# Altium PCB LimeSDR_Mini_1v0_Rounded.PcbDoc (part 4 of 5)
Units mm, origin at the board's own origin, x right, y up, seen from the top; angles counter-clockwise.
Board outline 69.3 x 52.3 mm, 8 copper layers (Top, L2, L3, L4, L5, L6, L7, Bottom), stack 1.555 mm thick; 371 components, 281 nets, 1644 pads, 778 vias.
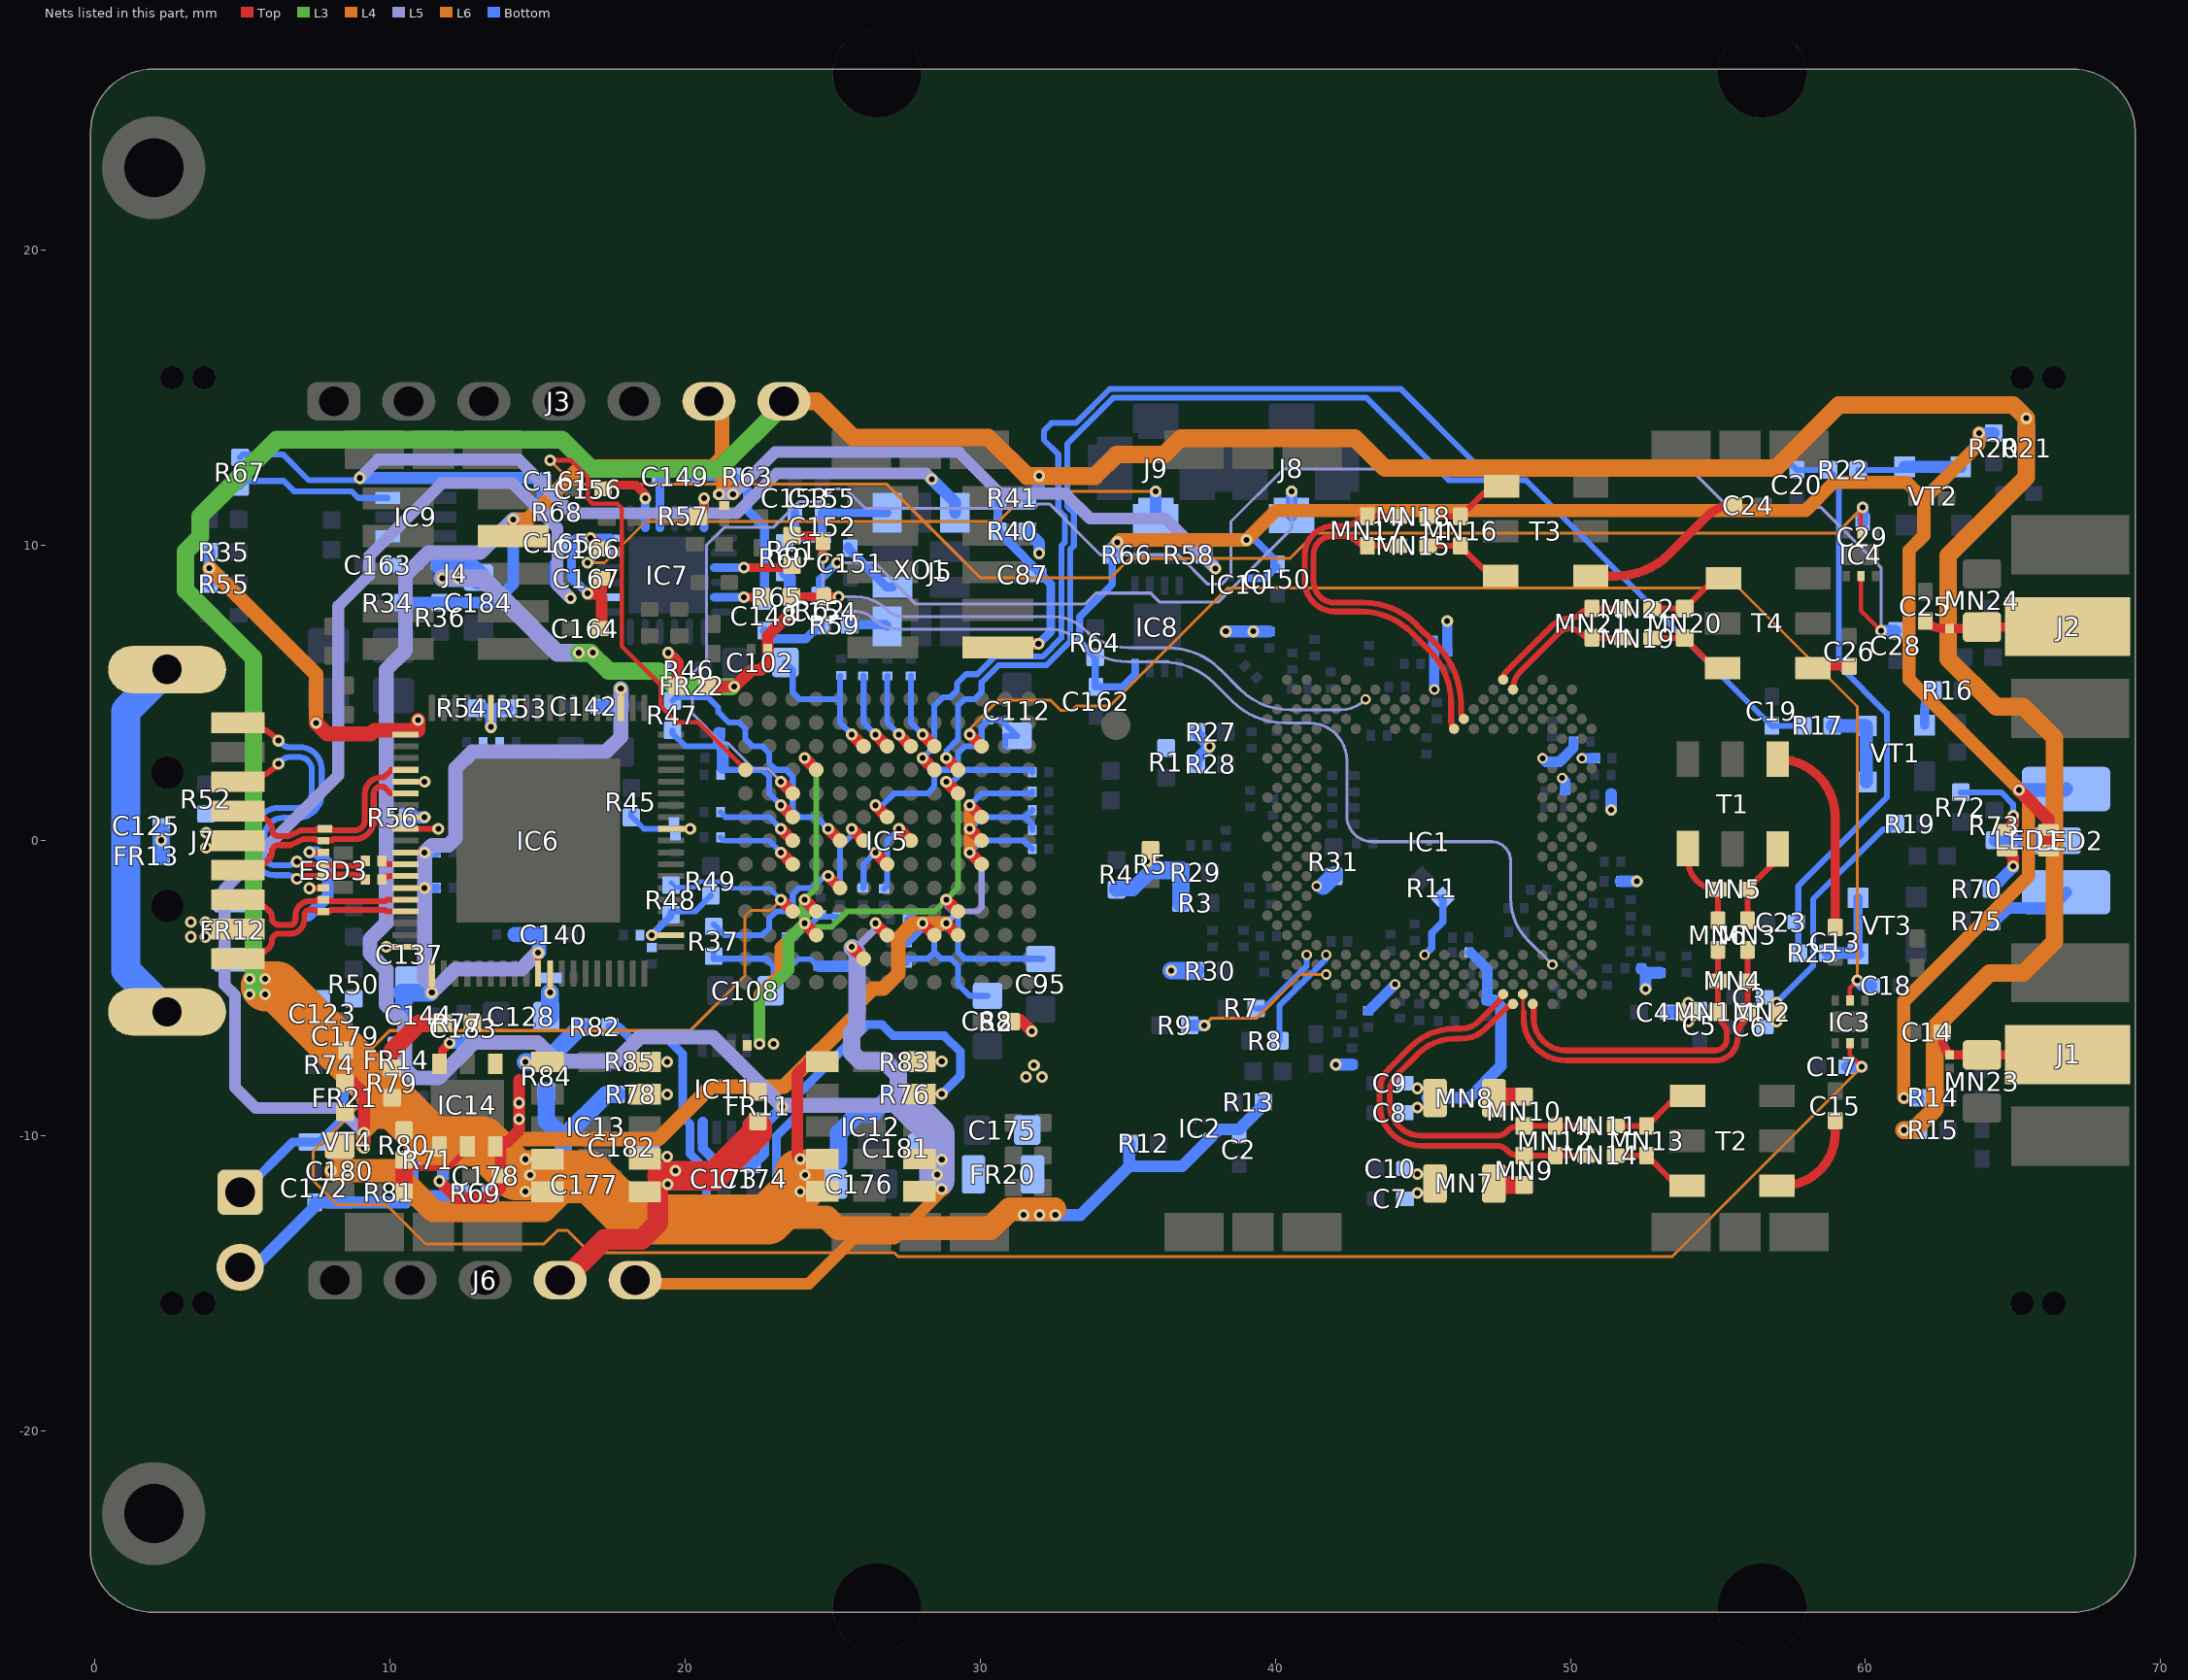
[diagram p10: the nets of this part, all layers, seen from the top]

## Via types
v1: diameter 0.4, hole 0.2, Top to Bottom, tented both sides, 544 vias
v2: diameter 0.4, hole 0.2, Top to Bottom, tented top, 113 vias
v3: diameter 0.35, hole 0.2, Top to Bottom, tented top, 87 vias
v4: diameter 0.5, hole 0.2, Top to Bottom, 25 vias
v5: diameter 0.5, hole 0.2, Top to Bottom, tented both sides, 8 vias
v6: diameter 0.35, hole 0.2, Top to Bottom, tented both sides, 1 vias

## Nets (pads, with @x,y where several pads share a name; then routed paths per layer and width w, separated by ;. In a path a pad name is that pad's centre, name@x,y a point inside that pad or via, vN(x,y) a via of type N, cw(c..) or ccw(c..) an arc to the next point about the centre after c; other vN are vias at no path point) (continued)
NetC82_1: C82.1 IC1.C21 | length 1.3
  Bottom w0.35: C82.1@43.15,-5.76 43.169,-5.76 v3(44.061,-4.868)
NetC83_1: C83.1 IC1.AF6 | length 1.5
  Bottom w0.35: v3(49.056,2.791) 49.173,2.674 49.635,2.674 50.108,3.147 C83.1@50.108,3.357
NetC84_1: C84.1 IC1.AF2 | length 0.5
  Bottom w0.35: v3(50.388,2.791) 50.844,2.791 C84.1@50.845,2.79
NetC85_1: C85.1 IC1.AD4 | length 0.5
  Bottom w0.35: v3(49.722,2.125) 49.825,2.022 C85.1@49.825,1.695
NetC86_1: C86.1 IC1.AN17 | length 1.6
  Bottom w0.34: C86.1@45.351,6.66 C86.1@45.351,6.768 ; C86.1@45.381,6.605 45.381,5.134 v3(45.393,5.122)
NetC87_2: C87.2 J5.10 R40.2 R41.2 | length 7.3
  Top w0.4: J5.10@30.6,6.515 30.75,6.665 v1(31.975,6.665)
  Bottom w0.3: R41.2@30.594,11.606 30.594,10.496 R40.2@30.6,10.49 32.4,8.69 32.4,7.09 v1(31.975,6.665)
NetC125_1: C125.1 FR13.2 J7.10 | length 12.8
  Bottom w1: J7.10@2.45,-5.8 1.05,-4.4 1.05,4.4 J7.10@2.45,5.8
NetC148_1: C148.1 C149.2 R63.2 | length 6.1
  Bottom w0.309: C149.2@20.175,12.34 R63.2@21.625,12.34 21.668,12.34 22.125,11.883 22.125,11.19 22.7,10.615 C148.1@22.7,8.115
NetC148_2: C148.2 R59.2 R62.2 | length 2.2
  Bottom w0.309: C148.2@22.7,7.115 22.975,6.84 24.09,6.84 24.568,7.318 R62.2@24.588,7.318
NetC149_1: C149.1 IC7.21 | length 1.8
  Bottom w0.3: IC7.21@19.15,10.6 IC7.21@19.15,10.925 19.15,12.315 C149.1@19.175,12.34
NetC151_2: C151.2 XO1.7 | length 2.1
  Bottom w0.3: C151.2@25.525,9.965 25.525,9.911 26.846,8.59 XO1.7@27.025,8.59
NetC153_2: C153.2 FR15.1 R60.1 | length 1.4
  Bottom w0.3: C153.2@23.725,11.115 23.725,10.265 FR15.1@24.245,10.265
NetC155_2: C155.2 FR15.2 XO1.9 | length 3.1
  Bottom w0.3: FR15.2@24.805,10.265 24.65,10.42 C155.2@24.65,11.115 XO1.9@26.85,11.115
NetC156_2: C156.2 IC7.20 | length 2.7
  Top w0.3: C156.2@17.225,11.915 17.36,12.05 18.336,12.05 18.65,11.736 v1(18.65,11.6)
  Bottom w0.3: IC7.20@18.65,10.6 IC7.20@18.65,10.925 v1(18.65,11.6)
NetC163_1: C163.1 FR17.2 IC9.4
NetC172_1: C172.1 J10.2 R69.2 R71.2 | length 9.8
  Bottom w0.4: J10.2@4.925,-14.455 5.403,-14.455 7.45,-12.408 C172.1@7.45,-12.26 10.545,-12.26 10.77,-12.035 ; R71.2@10.8,-10.835 10.77,-10.865 10.77,-12.035 ; R69.2@12.4,-11.935 12.3,-12.035 10.77,-12.035
NetC183_2: C183.2 IC14.3 | length 1.3
  Top w0.3: IC14.3@11.675,-7.56 11.775,-7.46 11.775,-7.11 v1(12.025,-6.86)
  Bottom w0.4: v1(12.025,-6.86) C183.2@12.5,-6.86
NetIC1_D28: IC1.D28 R9.1 | length 5.3
  L4 w0.1: v1(37.6,-6.257) 37.847,-6.01 39.375,-6.01 40.85,-4.535 v3(41.73,-4.535)
  Bottom w0.4: R9.1@37.1,-6.257 v1(37.6,-6.257)
NetIC1_F18: IC1.F18 R11.1 | length 2.2
  Bottom w0.25: v3(45.06,-3.869) 45.298,-3.631 45.298,-3.134 45.681,-2.751 45.681,-2.019 R11.1@45.63,-1.967
NetIC1_F28: IC1.F28 R8.1 | length 3.6
  Bottom w0.2: R8.1@40.15,-6.782 40.15,-5.585 41.73,-4.005 v3(41.73,-3.869)
NetIC1_F30: IC1.F30 R7.1 | length 2.7
  Bottom w0.2: R7.1@39.35,-5.682 39.628,-5.682 41.064,-4.246 v3(41.064,-3.869)
NetIC5_E5: IC5.E5 R37.2 | length 5.8
  Top w0.4: v2(24.85,-1.2) IC5.E5@25.25,-1.6
  Bottom w0.2: R37.2@20.975,-2.835 21.34,-3.2 22.616,-3.2 22.85,-2.966 22.85,-2.634 23.084,-2.4 23.416,-2.4 23.65,-2.166 23.65,-1.834 23.884,-1.6 24.322,-1.6 24.722,-1.2 v2(24.85,-1.2)
NetIC5_E7: IC5.E7 R47.2 | length 8.9
  Top w0.4: v2(24.85,0.4) IC5.E7@25.25,0
  Bottom w0.2: R47.2@19.575,4.74 19.7,4.865 20.766,4.865 21.125,4.506 21.125,4.359 21.484,4 21.84,4 22.05,3.79 22.05,3.434 22.284,3.2 22.616,3.2 22.85,2.966 22.85,2.634 23.084,2.4 23.416,2.4 23.65,2.166 23.65,1.034 23.884,0.8 24.45,0.8 v2(24.85,0.4)
NetIC6_27: IC6.27 R56.2 | length 1.2
  Top w0.2: IC6.27@10.525,0.8 v1(11.175,0.8)
  Bottom w0.4: R56.2@10.6,0.79 11.165,0.79 v1(11.175,0.8)
NetIC7_3: IC7.3 R61.2 | length 2.6
  Top w0.3: v1(22,9.25) 23.408,9.25 ccw(c23.408,9.557) R61.2@23.625,9.34
  Bottom w0.3: IC7.3@21,9.25 IC7.3@21.325,9.25 v1(22,9.25)
NetIC7_5: IC7.5 R65.2 | length 1.6
  Top w0.309: v1(22,8.25) 22.564,8.25 ccw(c22.564,8.301) R65.2@22.6,8.265
  Bottom w0.3: IC7.5@21,8.25 IC7.5@21.325,8.25 v1(22,8.25)
NetIC7_24: IC7.24 R57.1 | length 1.7
  Top w0.3: R57.1@20.45,10.99 20.65,11.19 v1(20.65,11.6)
  Bottom w0.3: IC7.24@20.65,10.6 IC7.24@20.65,10.925 v1(20.65,11.6)
NetIC9_6: IC9.6 R67.2 | length 5.3
  Bottom w0.2: R67.2@4.925,11.99 5.125,12.19 6.4,12.19 6.75,11.84 8.7,11.84 8.925,11.615 IC9.6@9.925,11.615
NetIC12_11: IC12.11 R83.2
  other v1: 28.701,-7.485
NetIC13_1: IC13.1 R82.1 R84.2 | length 2.4
  Bottom w0.6: v1(14.588,-7.495) 15.265,-7.495 R82.1@16.45,-6.31
NetIC13_10: IC13.10 R78.1
  other v1: 19.39,-8.595
NetIC13_11: IC13.11 R85.2
  other v1: 19.39,-7.495
NetIC14_4: IC14.4 R79.1 R80.2
NetIC14_5: IC14.5 R80.1 R81.1 | length 3.5
  Top w0.2: R80.1@10.6,-11.085 11.984,-11.085 12.625,-10.444 IC14.5@12.625,-10.36
  Top w0.6: R81.1@10.475,-11.91 R80.1@10.475,-10.81
NetJ7_7: J7.7 R52.2
  other v1: 3.775,-0.235 3.775,0.265
NetJ10_1: J10.1 R74.2 VT4.D | length 6.3
  Bottom w0.3: J10.1@4.925,-11.915 5.006,-11.915 6.711,-10.21 VT4.D@7.4,-10.21 7.625,-10.21 8.45,-9.385 R74.2@8.45,-7.61
NetLED1_3: LED1.3 R70.1 | length 1.7
  Top w0.4: LED1.3@64.8,-0.335 65,-0.535 v1(65,-0.86)
  Bottom w0.4: R70.1@64.275,-1.635 65,-0.91 v1(65,-0.86)
NetLED1_4: LED1.4 R72.1 | length 2.9
  Top w0.4: LED1.4@64.8,0.365 65,0.565 v1(65,0.84)
  Bottom w0.2: R72.1@63.225,1.64 64.598,1.64 65,1.238 v1(65,0.84)
NetLED2_C1: LED2.C1 R75.1 | length 3.1
  Bottom w0.4: R75.1@64.15,-2.735 64.375,-2.735 64.825,-2.285 66.265,-2.285 LED2.C1@66.8,-1.75
NetLED2_C2: LED2.C2 R73.1 | length 1.9
  Bottom w0.4: R73.1@64.375,0.015 64.39,0 LED2.C2@66.3,0
NetMN7_1: MN7.1 MN9.2 | length 1
  Top w0.6: MN7.1@47.412,-11.618 47.464,-11.67 MN9.2@48.435,-11.67
NetMN8_1: MN8.1 MN10.2 | length 1
  Top w0.6: MN8.1@47.412,-8.718 47.46,-8.67 MN10.2@48.435,-8.67
NetR16_2: R16.2 VT1.2 | length 1.3
  Bottom w0.309: VT1.2@62,3.915 62,4.408 cw(c62.982,4.408) R16.2@62.287,5.102
NetR17_1: R17.1 VT1.3 VT1.4 | length 3
  Bottom w0.45: R17.1@58.875,3.89 VT1.3@60.025,3.89 VT1.4@60.025,1.99
NetR22_2: R22.2 VT2.3 VT2.4 | length 3.5
  Bottom w0.2: R22.2@59.75,12.565 61.225,12.565 VT2.4@61.325,12.665
  Bottom w0.4: VT2.4@61.325,12.665 VT2.3@63.225,12.665
NetR25_1: R25.1 VT3.3 VT3.4 | length 2.9
  Bottom w0.309: VT3.4@59.75,-3.835 VT3.3@59.75,-1.935
  Bottom w0.4: R25.1@58.725,-3.81 59.725,-3.81 VT3.4@59.75,-3.835
NetR59_1: R59.1 XO1.6 | length 1.3
  Bottom w0.309: R59.1@25.575,7.315 26.8,7.315 XO1.6@26.85,7.265
PG_VCC1P8: IC12.10 R76.1 R82.2 | length 23.3
  Bottom w0.3: R82.2@17.45,-6.31 17.75,-6.31 18.125,-6.685 19.375,-6.685 19.925,-7.235 19.925,-9.36 20.175,-9.61 20.175,-9.91 20.175,-10.611 20.725,-11.161 20.725,-12.234 21.076,-12.585 22.574,-12.585 23.1,-12.059 23.1,-10.01 23.825,-9.285 23.825,-8.585 26.175,-6.235 26.676,-6.235 27.051,-6.61 28.787,-6.61 29.336,-7.159 29.336,-7.95 v1(28.701,-8.585)
REF_CLK_IN: J8.1 R62.1 | length 20.7
  L5 w0.1: v1(25.15,9.415) 26.425,9.415 27.825,8.015 33.55,8.015 33.925,8.39 35.775,8.39 36.075,8.09 38.075,8.09 40.55,10.565 v1(40.55,11.84)
  Bottom w0.3: R62.1@24.588,8.317 24.588,8.853 v1(25.15,9.415)
  Bottom w0.4: J8.1@40.55,11.015 v1(40.55,11.84)
REF_CLK_OUT: IC7.17 J9.1 | length 22
  L6 w0.1: v1(16.7,9.415) 17.275,9.415 18.675,10.815 30.625,10.815 31.65,11.84 v1(35.95,11.84)
  Bottom w0.25: v1(16.7,9.415) 17.035,9.75 IC7.17@17.475,9.75
  Bottom w0.4: J9.1@35.95,11.015 v1(35.95,11.84)
RFSW_RX_V1: C29.2 IC4.5 IC5.A10 | length 63
  Top w0.15: v1(15.425,12.89) 16.125,12.89 16.7,12.315 16.7,11.59 16.875,11.415 17.7,11.415 17.85,11.265 17.85,6.6 19.175,5.275 19.175,4.565 19.725,4.015 20.435,4.015 IC5.A10@22.05,2.4 ; IC4.5@59.85,10.415 v1@59.85,11.29
  L4 w0.1: v1(15.425,12.89) 16.225,12.09 26.825,12.09 30,8.915 34.425,8.915 35.075,9.565 40.5,9.565 41.35,10.415 59.025,10.415 v1(59.9,11.29)
  Bottom w0.4: C29.2@59.9,10.79 v1(59.9,11.29)
RFSW_RX_V2: C28.2 IC4.2 IC5.C9 | length 61.3
  Top w0.15: IC4.2@59.85,8.965 59.85,7.79 v1(60.525,7.115)
  Top w0.4: v2(23.25,2) IC5.C9@23.65,1.6
  L5 w0.1: v2(23.25,2) 22.81,2.44 22.315,2.44 21.44,3.315 21.24,3.315 20.25,4.305 20.25,5.67 20.725,6.145 20.725,10.015 21.325,10.615 22.992,10.615 23.867,11.49 24.59,11.49 25.025,11.925 25.44,11.925 26.1,11.265 31.825,11.265 31.975,11.415 32.35,11.415 34.075,9.69 36.72,9.69 37.72,8.69 38.175,8.69 38.5,9.015 38.5,10.815 40.275,12.59 54.075,12.59 55.375,11.29 58.5,11.29 60.525,9.265 v1(60.525,7.115)
  Bottom w0.4: v1(60.525,7.115) C28.2@61.025,7.115
RFSW_TX_V1: C18.2 IC3.5 IC5.L11 | length 45.4
  Top w0.15: IC3.5@59.475,-5.41 59.475,-4.985 v1(59.725,-4.735)
  Top w0.4: v2(29.65,3.6) IC5.L11@30.05,3.2
  L4 w0.1: v2(29.65,3.6) 29.65,3.79 30.625,4.765 32.38,4.765 32.73,4.415 33.1,4.415 33.25,4.565 34.391,4.565 38.391,8.565 55.709,8.565 59.725,4.549 v1(59.725,-4.735)
  Bottom w0.4: v1(59.725,-4.735) 59.9,-4.91 C18.2@60.2,-4.91
RFSW_TX_V2: C17.2 IC3.2 IC5.C4 R48.2 | length 85.2
  Top w0.15: IC3.2@59.475,-6.86 59.475,-7.26 v1(59.875,-7.66)
  Top w0.4: v2(23.25,-2) IC5.C4@23.65,-2.4
  L6 w0.1: v2(23.25,-2) 22.89,-2.36 22.225,-2.36 22.025,-2.56 22.025,-4.585 20.175,-6.435 9.991,-6.435 8.925,-7.501 8.925,-9.01 7.4,-10.535 7.4,-11.519 8.216,-12.335 9.875,-12.335 11.2,-13.66 15.225,-13.66 15.675,-13.21 16.025,-13.21 16.775,-13.96 27.085,-13.96 27.225,-14.1 53.435,-14.1 v1(59.875,-7.66)
  Bottom w0.15: R48.2@19.525,-1.41 19.69,-1.575 20.33,-1.575 20.52,-1.385 21.212,-1.385 21.437,-1.61 22.86,-1.61 v2(23.25,-2)
  Bottom w0.4: C17.2@59.375,-7.66 v1(59.875,-7.66)
RX: C25.2 ESD2.1 J2.1 MN24.1 | length 4.9
  Top w0.309: C25.2@62.025,7.44 62.028,7.437 ccw(c62.625,8.035) 62.625,7.19 ESD2.1@62.85,7.19 63.829,7.19 ccw(c63.829,7.361) MN24.1@63.95,7.24 66.815,7.24 ccw(c66.815,7.283) J2.1@66.845,7.252
RX1_H: C24.2 T3.4 | length 5.7
  Top w0.309: T3.4@50.69,8.97 51.553,8.97 ccw(c51.553,11.51) 53.349,9.714 54.629,10.994 cw(c55.525,10.098) C24.2@55.525,11.365
RX1_H_A_N: IC1.AJ15 MN17.1 MN18.2 | length 12.9
  Top w0.2: MN17.1@43.132,10.99 MN17.1@43.125,10.99 ; MN18.2@44.175,10.99 MN17.1@43.125,10.99 ; IC1.AJ15@46.059,3.79 cw(c46.3,4.031) 45.959,4.031 45.959,4.656 ccw(c43.394,4.656) 45.208,6.47 44.636,7.042 ccw(c42.89,5.295) 42.89,7.765 42.025,7.765 cw(c42.025,8.79) 41,8.79 41,9.69 cw(c41.97,9.69) 41.97,10.66 42.328,10.66 ccw(c42.328,11.279) 42.766,10.841 cw(c43.125,10.482) MN17.1@43.125,10.99
RX1_H_A_P: IC1.AK14 MN15.2 MN17.2 | length 12
  Top w0.2: MN15.2@44.175,9.99 MN17.2@43.125,9.99 cw(c43.125,10.498) 42.766,10.139 ccw(c42.328,9.701) 42.328,10.32 41.93,10.32 ccw(c41.93,9.69) 41.3,9.69 41.3,8.79 ccw(c42.025,8.79) 42.025,8.065 42.999,8.065 cw(c42.999,5.544) 44.782,7.327 45.448,6.66 cw(c43.411,4.623) 46.292,4.623 46.292,4.54 46.292,4.364 ccw(c46.633,4.364) IC1.AK14@46.392,4.123
RX1_H_B_N: MN16.1 MN18.1 T3.2 | length 2.8
  Top w0.2: MN18.1@45.175,10.99 MN16.1@46.225,10.99 ; MN16.1@46.275,10.99 47.033,11.748 cw(c47.665,11.117) T3.2@47.665,12.01
RX1_H_B_P: MN15.1 MN16.2 T3.1 | length 2.8
  Top w0.2: MN15.1@45.175,9.99 45.575,9.99 MN16.2@46.225,9.99 ; MN16.2@46.275,9.99 47.051,9.214 ccw(c47.64,9.803) T3.1@47.64,8.97
RX1_W: C26.2 T4.4 | length 1.3
  Top w0.309: T4.4@58.225,5.821 ccw(c58.191,5.821) T4.4@58.215,5.845 cw(c58.384,5.676) 58.384,5.915 C26.2@59.45,5.915
RX2_W_A_N: IC1.AP10 MN21.1 MN22.2 | length 5
  Top w0.2: IC1.AP10@47.739,5.47 IC1.AP10@47.724,5.455 cw(c48.147,5.455) 47.848,5.754 48.85,6.757 49.384,7.291 cw(c49.974,6.701) 49.974,7.535 ccw(c49.974,8.043) 50.333,7.684 ; 50.366,7.716 cw(c50.725,7.357) MN21.1@50.725,7.865 ; MN21.1@50.732,7.865 MN22.2@51.775,7.865
RX2_W_A_P: IC1.AN9 MN19.2 MN21.2 | length 4.8
  Top w0.2: IC1.AN9@48.072,5.137 IC1.AN9@48.057,5.122 cw(c48.928,5.122) 48.312,5.738 49.625,7.05 cw(c49.974,6.701) 49.974,7.195 cw(c49.974,6.687) 50.333,7.046 50.366,7.014 ccw(c50.725,7.373) 50.725,6.865 MN19.2@51.775,6.865
RX2_W_B_N: MN20.1 MN22.1 T4.2 | length 2.8
  Top w0.2: MN22.1@52.775,7.865 MN20.1@53.825,7.865 ; MN20.1@53.875,7.865 54.633,8.623 cw(c55.265,7.992) T4.2@55.265,8.885
RX2_W_B_P: MN19.1 MN20.2 T4.1 | length 3.2
  Top w0.2: MN19.1@52.775,6.865 53.175,6.865 MN20.2@53.825,6.865 ; MN20.2@53.875,6.865 54.633,6.107 ccw(c55.265,6.738) T4.1@55.265,5.845 ; T4.1@54.87,5.845 T4.1@55.215,5.845
RXPLL_CLK: C154.2 IC1.AM24 R65.1 | length 20.7
  Top w0.309: R65.1@23.6,8.265 C154.2@24.717,8.265 ; C154.2@24.7,8.265 v1(25.2,8.265)
  L5 w0.1: v1(25.2,8.265) 25.799,8.265 cw(c25.799,6.814) 26.825,7.84 ccw(c27.429,8.444) 27.429,7.59 32.499,7.59 cw(c32.499,6.139) 33.525,7.165 ccw(c35.034,8.674) 35.034,6.54 36.348,6.54 cw(c36.348,4) 38.144,5.796 38.806,5.134 ccw(c40.504,6.832) 40.504,4.431 42.203,4.431 ccw(c42.203,5.639) v3@43.057,4.784
  other v3: 43.062,4.789
TCXO_VC: C161.2 R67.1 R68.1 XO1.1 | length 34.3
  L5 w0.4: v1(8.975,12.29) 9.6,12.915 14.363,12.915 16.178,11.1 21.76,11.1 23.1,12.44 28.175,12.44 v1(28.365,12.25)
  Bottom w0.2: R67.1@4.925,12.99 5.025,13.09 6.375,13.09 7.25,12.215 8.9,12.215 v1(8.975,12.29)
  Bottom w0.4: v1(8.975,12.29) 15.075,12.29 C161.2@15.175,12.19 R68.1@15.175,11.14 ; v1(28.365,12.25) 29.15,11.465 XO1.1@29.15,11.115
TX: C14.2 ESD1.1 J1.1 MN23.1 | length 4.8
  Top w0.309: C14.2@62.6,-6.485 62.6,-6.656 ccw(c63.454,-6.656) ESD1.1@62.85,-7.26 MN23.1@63.95,-7.26 66.815,-7.26 ccw(c66.815,-7.217) J1.1@66.845,-7.248
TX1_1: C13.2 T1.4 | length 6.8
  Top w0.309: T1.4@57.02,2.765 cw(c57.02,0.81) 58.975,0.81 C13.2@58.975,-2.935
TX1_1_A_N: IC1.A7 MN1.1 MN4.1 MN6.2 | length 11.1
  Top w0.2: IC1.A7@48.723,-5.584 48.757,-5.618 48.757,-6.01 ccw(c49.857,-6.01) 49.857,-7.11 54.9,-7.11 ccw(c54.9,-6.706) 55.304,-6.706 55.304,-6.539 ccw(c54.796,-6.539) 55.155,-6.18 ; IC1.A7@48.723,-5.534 IC1.A7@48.758,-5.569 ; MN1.1@55,-5.99 55,-5.808 MN4.1@55,-4.75 MN6.2@55,-3.7 ; MN1.1@55.001,-5.815 ccw(c55.509,-5.815) 55.149,-6.175
TX1_1_A_P: IC1.B8 MN2.1 MN3.1 MN4.2 | length 12.3
  Top w0.11: 48.39,-5.769 48.39,-5.557 IC1.B8@48.39,-5.201
  Top w0.2: 48.414,-5.804 48.414,-6.01 ccw(c49.854,-6.01) 49.854,-7.45 54.9,-7.45 ccw(c54.9,-6.679) 55.671,-6.679 55.671,-6.566 cw(c56.179,-6.566) 55.819,-6.207 55.852,-6.175 ccw(c55.493,-5.815) MN2.1@56.001,-5.815 ; MN2.1@56,-5.8 56,-5.4 MN4.2@56,-4.75 MN3.1@56,-3.7
TX1_1_B_N: MN5.2 MN6.1 T1.2 | length 2.7
  Top w0.2: T1.2@53.98,-0.63 ccw(c55,-0.63) MN5.2@55,-1.65 MN6.1@55,-2.7
TX1_1_B_P: MN3.2 MN5.1 T1.1 | length 2.8
  Top w0.2: MN3.2@56,-2.7 MN5.1@56,-1.65 56.776,-0.874 ccw(c56.187,-0.285) T1.1@57.02,-0.285
TX1_2: C15.2 T2.4 | length 3.5
  Top w0.309: T2.4@57.049,-11.71 cw(c57.049,-11.642) T2.4@57,-11.69 57.195,-11.69 ccw(c57.195,-9.91) 58.975,-9.91 C15.2@58.975,-9.485
TX2_1_A_N: IC1.B10 MN9.1 MN12.2 MN14.1 | length 14
  Top w0.2: IC1.B10@47.724,-5.201 47.689,-5.236 ccw(c47.848,-5.394) 47.624,-5.394 46.891,-6.126 cw(c46.303,-5.538) 46.303,-6.37 46.075,-6.37 ccw(c46.075,-8.46) 44.597,-6.982 43.885,-7.695 ccw(c44.729,-8.539) 43.535,-8.539 43.535,-8.925 ccw(c44.95,-8.925) 44.95,-10.34 47.495,-10.34 cw(c47.495,-10.848) 47.854,-10.489 47.886,-10.521 ccw(c48.246,-10.162) 48.246,-10.67 MN9.1@48.435,-10.67 MN12.2@49.485,-10.67 MN14.1@50.535,-10.67
TX2_1_A_P: IC1.A9 MN10.1 MN11.2 MN12.1 | length 13.2
  Top w0.2: IC1.A9@48.057,-5.534 48.022,-5.569 cw(c47.864,-5.411) 47.864,-5.634 47.128,-6.37 cw(c46.308,-5.549) 46.308,-6.71 46.075,-6.71 ccw(c46.075,-8.46) 44.837,-7.223 44.125,-7.935 ccw(c44.729,-8.539) 43.875,-8.539 43.875,-8.925 ccw(c44.95,-8.925) 44.95,-10 47.495,-10 ccw(c47.495,-9.492) 47.854,-9.851 47.886,-9.819 cw(c48.246,-10.178) 48.246,-9.67 MN10.1@48.435,-9.67 48.835,-9.67 MN12.1@49.485,-9.67 MN11.2@50.535,-9.67
TX2_1_B_N: MN13.1 MN14.2 T2.1 | length 3.2
  Top w0.2: MN14.2@51.535,-10.67 51.935,-10.67 MN13.1@52.585,-10.67 53.344,-11.428 ccw(c53.975,-10.797) T2.1@53.975,-11.69 ; T2.1@53.605,-11.69 T2.1@53.95,-11.69
TX2_1_B_P: MN11.1 MN13.2 T2.2 | length 2.8
  Top w0.2: MN11.1@51.535,-9.67 MN13.2@52.585,-9.67 53.344,-8.912 cw(c53.975,-9.543) T2.2@53.975,-8.65
TX_LB_AT: C19.1 IC5.K10 R17.2 | length 44.4
  Top w0.4: v2(28.85,2.8) IC5.K10@29.25,2.4
  Bottom w0.2: v2(28.85,2.8) 28.85,3.034 29.25,3.434 29.25,3.766 29.25,4.566 29.484,4.8 29.816,4.8 30.05,5.034 30.05,5.366 30.624,5.94 32.24,5.94 33.05,6.75 33.05,9.866 33.175,9.991 33.175,11.099 32.95,11.324 32.95,13.44 34.525,15.015 43.075,15.015 45.875,12.215 48.5,12.215 C19.1@56.825,3.89 R17.2@57.875,3.89
TX_LB_SH: C20.1 C23.1 IC5.J10 R22.1 R25.2 | length 62
  Top w0.4: v2(28.05,2.8) IC5.J10@28.45,2.4
  Bottom w0.2: v2(28.05,2.8) 28.45,3.2 28.45,4.566 28.749,4.865 28.991,4.865 29.225,5.099 29.225,5.341 29.525,5.641 29.901,5.641 30.5,6.24 32.116,6.24 32.75,6.874 32.75,9.99 32.875,10.115 32.875,10.975 32.65,11.2 32.65,13.09 32.159,13.581 32.159,13.89 32.419,14.15 33.236,14.15 34.401,15.315 44.25,15.315 46.775,12.79 57.45,12.79 C20.1@57.675,12.565 R22.1@58.75,12.565 59.1,12.215 59.1,5.94 60.725,4.315 60.725,1.465 57.725,-1.535 R25.2@57.725,-3.81
TXPLL_CLK: C152.2 IC1.E5 R61.1 | length 35.1
  Top w0.309: R61.1@23.625,10.34 24.192,10.34 cw(c24.192,9.657) C152.2@24.675,10.14 v1(24.675,9.59)
  L5 w0.1: v1(24.675,9.59) 24.675,8.29 ccw(c25.2,8.29) 25.2,7.765 25.789,7.765 cw(c25.789,6.93) 26.379,7.521 ccw(c27.238,8.379) 26.501,7.414 ccw(c27.238,8.379) 27.238,7.165 32.451,7.165 cw(c32.451,6.141) 33.175,6.865 33.231,6.809 ccw(c35.027,8.605) 35.027,6.065 36.148,6.065 cw(c36.148,3.525) 37.944,5.321 38.531,4.734 ccw(c40.327,6.53) 40.327,3.99 41.15,3.99 cw(c41.15,2.715) 42.425,2.715 42.425,0.84 ccw(c43.3,0.84) 43.3,-0.035 47.325,-0.035 cw(c47.325,-0.685) 47.975,-0.685 47.975,-1.96 ccw(c49.974,-1.96) 48.56,-3.373 v3(49.389,-4.202)
USB_D_N: ESD3.2 IC6.25 J7.2 | length 7.6
  Top w0.2: J7.2@4.85,-1 5.022,-1 ccw(c5.022,0.238) 5.897,-0.638 ccw(c5.65,-0.39) 6,-0.39 cw(c6.24,-0.39) 6.24,-0.15 6.625,-0.15 7.05,0.05 7.48,0.05 7.53,0 ESD3.2@7.742,0 ; ESD3.2@7.818,0 8.03,0 8.08,0.05 8.805,0.05 ccw(c8.805,0.695) 9.45,0.695 9.45,1.59 cw(c9.695,1.59) 9.695,1.835 ; 9.7,1.835 cw(c9.7,1.618) 9.853,1.772 10.025,1.6 IC6.25@10.525,1.6
USB_D_P: ESD3.1 IC6.23 J7.3 | length 8.2
  Top w0.2: J7.3@4.65,0.965 4.685,1 J7.3@4.85,1 J7.3@5.022,1 ; J7.3@5.39,1 J7.3@5.022,1 ; ESD3.1@7.742,0.4 7.53,0.4 7.48,0.35 6.975,0.35 6.55,0.15 6.24,0.15 cw(c6.24,0.39) 6,0.39 ccw(c5.65,0.39) 5.897,0.638 ccw(c5.022,-0.238) J7.3@5.022,1 ; ESD3.1@7.818,0.4 8.03,0.4 8.08,0.35 8.805,0.35 ccw(c8.805,0.695) 9.15,0.695 9.15,1.59 cw(c9.7,1.59) 9.7,2.14 ccw(c9.7,2.357) 9.853,2.203 10.05,2.4 IC6.23@10.525,2.4
USB_GND: C125.2 ESD3.6 FR13.1 NT1.1 | length 1.3
  Top w0.2: v1(7.275,-1.615) cw(c7.311,-1.651) 7.311,-1.6 ESD3.6@7.742,-1.6
  Bottom w0.6: FR13.1@2.252,-0.515 C125.2@2.252,0.29
  other v1: 2.25,0.015
USB_SSRX_N: ESD3.7 IC6.34 J7.8 | length 7.2
  Top w0.2: J7.8@5.39,-2 J7.8@4.85,-2 5.022,-2 cw(c5.022,-3.238) 5.897,-2.362 cw(c5.65,-2.61) 6,-2.61 ccw(c6.24,-2.61) 6.24,-2.85 6.625,-2.85 ccw(c6.625,-2.675) 6.8,-2.675 6.8,-2.535 cw(c7.285,-2.535) 7.285,-2.05 7.48,-2.05 7.53,-2 ESD3.7@7.742,-2 7.955,-2 8.005,-2.05 9.85,-2.05 9.9,-2 IC6.34@10.525,-2
USB_SSRX_P: ESD3.8 IC6.35 J7.9 | length 6.7
  Top w0.2: J7.9@4.2,-4 J7.9@4.372,-4 ; J7.9@5.022,-4 ccw(c5.022,-2.762) 5.897,-3.638 ccw(c5.65,-3.39) 6,-3.39 cw(c6.24,-3.39) 6.24,-3.15 6.625,-3.15 ccw(c6.625,-2.675) 7.1,-2.675 7.1,-2.535 cw(c7.285,-2.535) 7.285,-2.35 7.48,-2.35 7.53,-2.4 ESD3.8@7.742,-2.4 7.955,-2.4 8.005,-2.35 9.85,-2.35 9.9,-2.4 IC6.35@10.525,-2.4
USB_SSTX_N: C121.1 ESD3.4 J7.5 | length 11.5
  Top w0.2: J7.5@4.85,4 cw(c4.85,2.153) 6.156,3.459 v1(6.225,3.39) ; v1(6.85,-0.71) ccw(c7.067,-0.493) 7.067,-0.8 ESD3.4@7.742,-0.8 7.955,-0.8 8.005,-0.85 8.772,-0.85 ccw(c8.772,-0.287) C121.1@9.17,-0.685 C121.1@9.153,-0.685
  Bottom w0.2: v1(6.225,3.39) 6.335,3.28 ccw(c6.6,3.544) 6.6,3.17 6.935,3.17 cw(c6.935,2.415) 7.69,2.415 7.69,1.59 cw(c6.875,1.59) 6.875,0.775 6.385,0.775 ccw(c6.385,0.14) 5.75,0.14 5.75,-0.48 ccw(c6.1,-0.48) 6.1,-0.83 6.56,-0.83 ccw(c6.56,-0.42) v1(6.85,-0.71)
USB_SSTX_P: C122.1 ESD3.5 J7.6 | length 11.5
  Top w0.2: J7.6@4.85,2 ccw(c4.85,3.847) 6.156,2.541 v1(6.225,2.61) ; v1(6.85,-1.29) cw(c7.067,-1.507) 7.067,-1.2 ESD3.5@7.742,-1.2 7.955,-1.2 8.005,-1.15 8.772,-1.15 cw(c8.772,-1.713) C122.1@9.17,-1.315 C122.1@9.153,-1.315
  Bottom w0.2: v1(6.225,2.61) 6.335,2.72 cw(c6.6,2.456) 6.6,2.83 6.935,2.83 cw(c6.935,2.415) 7.35,2.415 7.35,1.59 cw(c6.875,1.59) 6.875,1.115 6.244,1.115 ccw(c6.244,0.281) 5.41,0.281 5.41,-0.48 ccw(c6.1,-0.48) 6.1,-1.17 6.56,-1.17 cw(c6.56,-1.58) v1(6.85,-1.29)
USB_SSTXI_N: C121.2 IC6.31 | length 0.8
  Top w0.2: C121.2@9.73,-0.685 ccw(c10.008,-0.407) 10.008,-0.8 IC6.31@10.525,-0.8
USB_SSTXI_P: C122.2 IC6.32 | length 0.8
  Top w0.2: C122.2@9.73,-1.315 cw(c10.008,-1.593) 10.008,-1.2 IC6.32@10.525,-1.2
USB_VBUS: C123.1 ESD3.3 FR12.1 J7.1 R50.2 | length 3.3
  Top w0.2: v1(7.275,-0.385) ccw(c7.311,-0.349) 7.311,-0.4 ESD3.3@7.742,-0.4
  Bottom w0.4: 7.238,-2.548 7.9,-1.885 7.9,-0.76 7.525,-0.385 v1(7.275,-0.385)
  other v1: 3.25,-3.26 3.75,-3.26 3.25,-2.76 3.75,-2.76
VCC1P8: C108.2 C109.1 C110.1 C111.1 C173.2 C174.1 C181.2 FR16.1 FR20.1 IC5.F2 IC5.G3 IC11.8 IC12.7 IC12.8 J3.6 J4.4 J6.5 R34.2 R36.2 R37.1 R58.2 | length 114.3
  Top w0.4: J4.4@14.175,10.325 v1(14.175,10.88) ; v1(25.65,-3.6) IC5.F2@26.05,-4 ; v1(26.45,-2.8) IC5.G3@26.85,-3.2
  L4 w0.4: J6.5@18.311,-15.01 24.2,-15.01 25.725,-13.485 27.101,-13.485 v1@28.701,-11.885
  L5 w0.25: v1@25.84,-3.6 26.45,-2.99 v1(26.45,-2.8)
  L5 w0.4: v1(21.15,11.74) v1(21.625,11.74) 23.05,13.165 29.275,13.165 30.675,11.765 32.875,11.765 33.725,10.915 36.275,10.915 v1(37.975,9.215) ; v1@25.775,-3.725 v1(25.65,-3.6) v1@25.84,-3.6
  L5 w0.5: v1(14.175,10.88) 13.06,9.765 11.3,9.765 10.525,8.99 10.525,6.44 9.875,5.79 9.875,-2.785 9.325,-3.335 9.325,-3.828 9.875,-4.378 9.875,-5.563 10.5,-6.188 10.5,-7.705 10.83,-8.035 11.647,-8.035 12.847,-6.835 15,-6.835 15.634,-7.469 17.672,-7.469 18.481,-6.66 20.95,-6.66 23.26,-8.97 26.89,-8.97 27.225,-8.635
  L5 w0.6: v1@25.675,-3.635 25.825,-3.785 25.825,-6.335 25.65,-6.51 25.65,-7.185 25.925,-7.46 26.75,-7.46 27.225,-7.935 27.225,-8.635
  L5 w1.2: 27.425,-8.81 28.539,-9.924 v1@28.539,-11.51
  L6 w0.5: v1(14.175,10.88) 14.665,10.88 16.46,12.675 20.94,12.675 ; J3.6@20.811,14.89 21.25,14.451 21.25,12.985 20.94,12.675 ; 21.4,11.815 21.3,11.915 21.3,12.315 21,12.615 20.94,12.675
  Bottom w0.17: 22.995,-4.255 23.1,-4.15 23.702,-4.15 23.837,-4.015 24.285,-4.015 C110.1@24.525,-4.255
  Bottom w0.2: R37.1@20.975,-3.835 20.975,-4 22.74,-4 22.995,-4.255 C108.2@22.995,-5.235
  Bottom w0.35: IC11.8@20.6,-9.535 20.6,-10.435 21.125,-10.96 C174.1@22.325,-10.96 22.675,-10.61 22.675,-9.635 v1(23.3,-9.01)
  Bottom w0.4: R34.2@10.425,8.065 13.55,8.065 14.175,8.69 v1(14.175,10.88) ; C110.1@24.544,-4.255 C109.1@25.2,-4.255 25.775,-4.255 25.775,-3.725 v1(25.65,-3.6) ; R58.2@37.575,9.69 v1@37.9,9.365
  other v1: 28.701,-11.81 28.539,-11.32 28.701,-10.81
VCC1P8_LMS: C3.1 C4.2 C5.1 C6.2 C7.1 C8.1 C9.2 C10.2 C175.2 FR1.2 FR2.1 FR3.1 FR4.2 FR5.2 FR6.2 FR7.2 FR8.2 FR20.2 MN1.2 MN2.2 MN7.2 MN8.2 R19.2 R26.2 R32.2 R33.1 | length 21.2
  Bottom w0.2: v1(56.985,-5.485) 58.225,-4.245 58.225,-1.985 60.588,0.378 60.812,0.378 R19.2@61.012,0.577
  Bottom w0.35: FR4.2@45.826,6.391 v1(45.826,7.441) ; FR6.2@46.614,-3.785 47.185,-4.356 FR7.2@47.185,-4.51 FR8.2@47.185,-5.405
  Bottom w0.4: v1(38.325,7.091) R33.1@39.801,7.091 ; v1(42.056,-7.589) R26.2@42.606,-7.589 ; 45.142,-8.718 46.567,-8.718 47.65,-7.635 47.65,-5.635 47.42,-5.405 FR8.2@47.175,-5.405 ; v1(51.38,1.04) FR3.1@51.38,1.59 ; FR2.1@51.704,-1.376 v1(52.254,-1.376) ; FR1.2@52.411,-4.334 FR1.2@52.555,-4.478 ; v1(52.555,-5.028) FR1.2@52.555,-4.478 ; R32.2@53.046,-4.478 FR1.2@52.555,-4.478 ; C4.2@53.325,-5.81 53.875,-5.81
  other v1: 44.817,-11.943 44.817,-11.293 44.817,-9.043 44.817,-8.393 31.55,-8.01 32.1,-8.01 31.825,-7.61 54,-6.135 56.985,-6.135 54,-5.485 39.251,7.091
VCC3P3: C102.2 C103.1 C104.1 C105.1 C106.1 C107.1 C112.2 C113.1 C114.1 C115.1 C116.1 C117.1 C118.1 C119.1 C120.1 C128.2 C129.2 C130.1 C131.2 C132.1 C133.2 C134.1 C135.2 C136.1 C150.1 C162.1 C178.2 C182.2 FR11.1 FR22.1 IC5.C6 IC5.C7 IC5.C8 IC5.F7 IC5.F11 IC5.G6 IC5.G8 IC5.G11 IC5.H7 IC5.H11 IC5.J11 IC6.14 IC6.20 IC6.24 IC6.28 IC6.38 IC6.49 IC6.59 IC6.68 IC8.8 IC10.A1 IC13.7 IC13.8 IC14.1 IC14.6 J6.4 LED1.1 LED1.2 LED2.A R14.1 R20.1 R35.1 R40.1 R45.1 R46.1 R47.1 R48.1 R49.1 R53.2 R54.2 R55.2 R64.1 R66.1 R71.1 R77.1 | length 155.6
  Top w0.2: v1(9.875,-3.6) IC6.38@10.525,-3.6 ; IC6.28@10.525,0.4 v1(11.64,0.4) ; IC6.24@10.525,2 v1(11.175,2) ; v1(13.425,3.85) IC6.14@13.425,4.5 ; v1(15.425,-5.15) IC6.49@15.425,-4.5 ; v1(18.875,-3.2) IC6.59@19.525,-3.2 ; IC6.68@19.525,0.4 v1(20.175,0.4)
  Top w0.4: v1(11.675,-11.535) 12.25,-12.11 13.4,-12.11 13.75,-11.76 13.75,-10.21 13.975,-10.21 14.375,-9.81 v1(14.375,-9.435) v1(14.375,-8.885) 14.375,-8.101 ; v1(19.425,6.365) 19.75,6.04 FR22.1@19.75,5.24 ; v1(23.25,-0.4) IC5.C6@23.65,-0.8 ; v1(23.25,0.4) IC5.C7@23.65,0 ; v1(23.25,1.2) IC5.C8@23.65,0.8 ; v1(25.65,0.4) IC5.F7@26.05,0 ; v1(25.65,3.6) IC5.F11@26.05,3.2 ; v1(26.45,-0.4) IC5.G6@26.85,-0.8 ; v1(26.45,1.2) IC5.G8@26.85,0.8 ; v1(26.45,3.6) IC5.G11@26.85,3.2 ; v1(27.25,0.4) IC5.H7@27.65,0 ; v1(27.25,3.6) IC5.H11@27.65,3.2 ; v1(28.05,3.6) IC5.J11@28.45,3.2
  Top w0.45: v1(65.2,1.715) 66.2,0.715 LED1.1@66.2,-0.335
  Top w0.5: v1(7.5,3.99) 7.875,3.615 9.35,3.615 9.475,3.74 10.937,3.74 10.95,3.753 v1(10.95,4.09)
  Top w0.7: J6.4@15.768,-14.89 15.894,-14.89 17.274,-13.51 18.525,-13.51 19.075,-12.96 IC13.7@19.075,-11.86 ; 21.025,-11.21 21.175,-11.36
  Top w1: 19.228,-11.355 21.025,-11.355 ; 21.18,-11.155 22.45,-9.885 FR11.1@22.45,-9.71
  L4 w0.45: v1(34.65,10.115) 34.725,10.19 v1(39.025,10.19) 40.025,11.19 57.975,11.19 58.925,12.14 61.4,12.14 61.975,11.565 ; v1(61.3,-8.71) 61.3,-5.435 65.525,-1.21 65.525,1.39 v1(65.2,1.715) 65.2,1.74 61.475,5.465 61.475,9.84 61.975,10.34 61.975,11.565 ; v1(63.85,13.815) 63.85,13.44 61.975,11.565
  L4 w0.5: v1@3.9,9.24 7.5,5.64 v1(7.5,3.99)
  Bottom w0.19: R45.1@18.175,0.965 18.175,0.84 18.61,0.405 20.17,0.405 v1(20.175,0.4) ; C116.1@21.205,0.115 21.325,-0.005 22.855,-0.005 v1(23.25,-0.4)
  Bottom w0.2: R48.1@19.525,-2.51 19.525,-2.4 20.341,-2.4 20.875,-1.866 R49.1@20.875,-1.86 ; R47.1@19.575,3.74 19.575,3.634 20.009,3.2 21.087,3.2 21.15,3.263 ; C120.1@21.205,0.965 21.37,0.8 22.85,0.8 v1(23.25,0.4) ; 21.28,2.465 21.345,2.4 22.616,2.4 22.85,2.166 22.85,1.6 v1(23.25,1.2) ; C102.2@23.4,6.04 23.65,5.79 23.65,5.034 23.884,4.8 25.231,4.8 25.25,4.781 ; C113.1@25.25,-1.605 25.25,-0.21 25.65,0.19 v1(25.65,0.4) ; C117.1@25.27,5.581 25.25,5.561 25.25,4.781 ; v1(25.65,3.6) 25.25,4 25.25,4.781 ; C115.1@26.025,-1.605 26.05,-1.58 26.05,-0.8 v1(26.45,-0.4) ; C118.1@26.04,5.581 26.05,5.571 26.05,4 v1(26.45,3.6) ; v1(26.45,1.2) 26.684,1.2 27.084,1.6 28.216,1.6 28.45,1.834 28.45,2.166 28.684,2.4 29.016,2.4 29.25,2.634 29.25,2.966 29.484,3.2 29.816,3.2 30.05,3.434 30.05,3.86 C103.1@30.275,4.085 30.715,4.085 C112.2@31.25,3.55 30.85,3.55 C112.2@30.85,3.2 ; C119.1@26.75,-1.63 26.85,-1.53 26.85,0 v1(27.25,0.4) ; C114.1@26.86,5.581 26.85,5.571 26.85,4 v1(27.25,3.6) ; C107.1@27.65,5.585 27.65,4 v1(28.05,3.6)
  Bottom w0.25: v1(18.875,-3.2) 19.525,-2.55 R48.1@19.525,-2.51 ; R66.1@34.475,9.69 34.475,8.69 33.375,7.59 33.375,6.74 R64.1@33.9,6.215 33.9,5.24 C162.1@33.925,5.215 34.825,5.215 35.25,5.64 IC8.8@35.25,5.84 IC8.8@35.25,6.015 ; IC10.A1@39.025,8.89 39.65,8.89 C150.1@40.05,9.29 ; v1(39.025,10.19) 39.325,10.19 39.95,9.565 C150.1@39.95,9.365
  Bottom w0.4: R55.2@3.875,8.69 v1(3.875,9.24) R35.1@3.875,9.79 ; v1(11.675,-11.535) 11.8,-11.41 R71.1@11.8,-10.835 ; R54.2@12.95,4.49 13.175,4.49 13.425,4.24 ; v1(13.425,3.85) 13.425,4.24 ; R53.2@13.975,4.49 13.675,4.49 13.425,4.24 ; v1(19.425,6.365) 19.675,6.115 R46.1@19.675,5.79 ; C106.1@21.15,3.65 21.15,3.263 21.28,3.133 21.28,2.465 ; R40.1@31.6,10.49 32,10.09 v1(32,9.74) ; R66.1@34.475,9.69 34.475,9.94 v1(34.65,10.115) ; v1(61.3,-8.71) R14.1@61.8,-8.71 ; v1(63.85,13.815) R20.1@64.35,13.815
  Bottom w0.45: v1(65.2,1.715) 66.765,1.715 LED2.A@66.8,1.75
  Bottom w0.6: C128.2@15.425,-5.96 v1(15.425,-5.15)
  other v1: 19.415,-11.645 19.678,-11.18 19.4,-10.71
VCC3P3_CLK: C184.2 FR17.1 FR19.1 FR22.2 R60.2 | length 19.4
  Top w0.4: FR22.2@20.75,5.24 20.77,5.22 v1(21.67,5.22) 21.692,5.22 22.255,5.783 22.574,5.783 22.805,6.014 FR19.1@22.805,6.49 22.805,6.945 v1(23.525,7.665)
  L3 w0.6: v1(16.4,6.365) 16.801,6.365 17.416,5.75 19.115,5.75 19.645,5.22 v1@21.575,5.22
  L5 w0.6: v1(11.775,8.89) 13.15,8.89 15.675,6.365 v1@16.775,6.365
  Bottom w0.4: v1@16.4,6.37 v1(16.88,6.37) ; R60.2@23.375,9.09 23.55,8.915 23.55,7.69 v1(23.525,7.665)
  Bottom w0.8: 11.775,9.365 12.55,9.365 C184.2@13,8.915
  other v1: 12.325,8.89
VCC3P3A: C95.2 C96.1 C97.1 C98.1 C99.1 C100.1 C101.1 FR11.2 IC5.D3 IC5.D4 IC5.D10 IC5.K4 IC5.K9 | length 40.4
  Top w0.4: v1(24.05,-2.8) IC5.D3@24.45,-3.2 ; v1(24.05,-2) IC5.D4@24.45,-2.4 ; v1(24.05,2.8) IC5.D10@24.45,2.4 ; v1(28.85,-2) IC5.K4@29.25,-2.4 ; v1(28.85,2) IC5.K9@29.25,1.6
  L3 w0.2: v1@23.938,-2.922 24.962,-2.922 25.484,-2.4 28.45,-2.4 v1(28.85,-2) 29.25,-1.6 29.25,1.6 v1(28.85,2) ; v1(24.05,-2) 24.45,-1.6 24.45,2.4 v1(24.05,2.8)
  L3 w0.4: v1(22.525,-6.885) 22.525,-5.36 23.5,-4.385 23.5,-3.36 23.938,-2.922 24.05,-2.81 v1(24.05,-2.8) v1(24.05,-2)
  L6 w0.4: v1(22.525,-6.885) 22.525,-5.21 23.225,-4.51 23.225,-3.625 v1(24.05,-2.8)
  Bottom w0.2: C99.1@23.361,-3.255 C99.1@23.45,-3.255 23.905,-2.8 v1(24.05,-2.8) 24.29,-2.8 C98.1@24.525,-2.565 ; v1(24.05,-2) 24.525,-2.475 C98.1@24.525,-2.565 ; C98.1@24.6,-2.49 C98.1@24.525,-2.565 ; C97.1@25.15,-2.58 24.525,-2.58 C98.1@24.525,-2.565 ; C96.1@27.53,-2.66 27.79,-2.4 28.45,-2.4 v1(28.85,-2) 28.85,-2.19 29.25,-2.59 29.25,-3.766 29.484,-4 32.115,-4 C95.2@32.125,-4.01 ; v1(28.85,2) 29.085,2 29.25,2.165 ; 29.25,2.166 29.484,2.4 31.77,2.4 C100.1@31.77,2.315
  other v1: 23,-6.885
VCC5P0_USB: C176.2 C177.2 FR12.2 IC12.1 IC12.4 IC12.5 IC13.4 IC13.5 J3.7 R15.1 R21.1 R41.1 R69.1 R76.2 R78.2 R84.1 | length 151.2
  Top w0.4: v1(23.899,-10.785) 23.8,-10.686 23.8,-7.91 24.225,-7.485 IC12.1@24.65,-7.485
  L3 w0.6: 5.375,-4.985 5.375,6.19 3.075,8.49 3.075,9.79 3.575,10.29 3.575,10.99 6.175,13.59 15.825,13.59 16.825,12.59 21.154,12.59 J3.7@23.354,14.79
  L4 w0.6: J3.7@23.354,14.89 24.469,14.89 25.694,13.665 30.275,13.665 31.584,12.356 v1(31.994,12.356) 33.891,12.356 34.625,13.09 36.25,13.09 36.8,13.64 42.697,13.64 43.712,12.625 56.96,12.625 59.1,14.765 65,14.765 v1(65.45,14.315) 65.45,12.315 62.8,9.665 62.8,6.165 64.425,4.54 65.35,4.54 66.4,3.49 66.4,-3.435 65.35,-4.485 64.2,-4.485 62.35,-6.335 62.35,-9.085 61.628,-9.807 v1(61.3,-9.807)
  L4 w1.7: 5.8,-4.935 6.175,-4.935 11.425,-10.185 13.125,-10.185 14.275,-11.335 v1(14.75,-11.335) 16.725,-11.335 18.225,-12.835 22.8,-12.835 23.875,-11.76 v1@23.875,-11.285
  Bottom w0.4: R41.1@31.594,11.606 31.994,12.006 v1(31.994,12.356) ; v1(61.3,-9.807) R15.1@61.8,-9.807 ; R21.1@65.45,13.815 v1(65.45,14.315)
  Bottom w0.6: R84.1@15.3,-8.485 15.3,-9.48 15.875,-10.055 ; 15.875,-10.935 15.875,-10.055 ; R78.2@17.664,-8.595 17.335,-8.595 15.875,-10.055 ; 25.2,-10.835 25.2,-9.91 25.85,-9.26 26.351,-9.26 26.95,-8.661 R76.2@26.95,-8.585
  other v1: 14.588,-11.895 23.899,-11.885 24.064,-11.335 14.588,-10.795 5.25,-5.21 5.775,-5.21 5.25,-4.685 5.775,-4.685
VD10_FT: C137.2 C138.2 C139.1 C140.1 C141.1 C142.1 C143.1 C144.1 FR14.1 IC6.3 IC6.30 IC6.33 IC6.39 IC6.48 | length 28.9
  Top w0.2: IC6.33@10.525,-1.6 v1(11.175,-1.6) ; IC6.30@10.525,-0.4 v1(11.175,-0.4) ; v1(11.425,-5.15) IC6.39@11.425,-4.5 ; IC6.48@15.025,-4.5 v1@15.025,-3.85 ; IC6.3@17.825,4.5 v1(17.825,5.15)
  L5 w0.5: v1@15,-3.8 14.775,-4.025 14.775,-4.028 14.453,-4.35 12.225,-4.35 v1(11.425,-5.15) 11.425,-4.91 11.175,-4.66 v1(11.175,-0.4) 11.415,-0.16 11.975,-0.16 12.225,0.09 12.225,2.449 12.791,3.015 17.328,3.015 17.825,3.512 v1(17.825,5.15)
  Bottom w0.3: v1(11.175,-1.6) C143.1@11.585,-1.6 ; v1(11.175,-0.4) C141.1@11.585,-0.4
  Bottom w0.4: C142.1@17.075,4.55 C139.1@17.87,4.55 ; v1(17.825,5.15) 17.895,5.08 C139.1@17.895,4.55
  Bottom w0.5: C138.2@14.225,-3.175 C140.1@15.05,-3.175 v1@15.05,-3.775
  Bottom w0.6: C137.2@10.4,-5.15 v1@11.35,-5.15 ; C144.1@10.475,-5.91 C137.2@10.475,-5.15
  other v1: 15.025,-3.8
VDIO_LMS: C2.1 C180.2 FR21.2 IC2.A1 R1.2 R2.2 R3.1 R4.1 R5.2 R12.1 R13.1 R27.1 R28.1 R29.1 R30.1 R31.1 | length 44.2
  Top w0.4: R2.2@31.05,-6.06 31.35,-6.06 v1(31.75,-6.46) ; v1(35.65,-0.707) 35.775,-0.582 R5.2@35.775,-0.31
  L6 w0.7: 11.451,-12.575 15.235,-12.575
  L6 w0.8: v1@8.175,-11.185 10.111,-11.185 11.451,-12.525 ; 15.235,-12.525 15.875,-11.885 17.4,-11.885 18.275,-12.76 24.8,-12.76 25.175,-13.135 30.35,-13.135 31,-12.485 32.525,-12.485
  Bottom w0.4: v1(31.475,-12.685) 33.4,-12.685 35.05,-11.035 ; R12.1@35.05,-10.26 35.05,-11.035 ; R28.1@37.322,2.59 37.322,2.737 v1(37.775,3.19) 37.326,3.639 R27.1@37.326,3.686 ; R13.1@39.6,-8.86 39.6,-8.96 38.775,-9.785 38.096,-9.785 36.846,-11.035 35.05,-11.035
  Bottom w0.5: R4.1@34.625,-1.66 34.625,-1.632 35.175,-1.632 35.8,-1.007
  Bottom w0.6: 35.8,-1.007 36.801,-1.007 36.801,-1.014 R3.1@36.8,-2.11 ; v1(36.475,-4.407) R30.1@37.3,-4.407 ; 41.627,-1.538 R31.1@42.001,-1.164
  other v1: 32.013,-12.685 32.55,-12.685 8,-11.185 8.55,-11.185
  other v3: 41.401,-1.539
VDIO_LMS_FPGA: C88.2 C89.1 C90.1 C91.1 C92.1 C93.1 C94.1 C179.2 FR18.1 FR21.1 IC5.J3 IC5.K3 IC5.L6 IC5.L7 IC5.L8 R77.2 R79.2 | length 88.1
  Top w0.4: FR21.1@8.725,-8.16 9.118,-8.553 v1(9.118,-9.903) v1(9.118,-10.41) ; v1(28.05,-2.8) IC5.J3@28.45,-3.2 ; v1(28.85,-2.8) IC5.K3@29.25,-3.2 ; v1(29.65,-0.4) IC5.L6@30.05,-0.8 ; v1(29.65,0.4) IC5.L7@30.05,0 ; v1(29.65,1.2) IC5.L8@30.05,0.8
  Top w0.6: 10.087,-7.098 11,-6.185 R77.2@11.8,-6.185
  L5 w0.2: v1(28.85,-2.8) 29.25,-2.4 29.91,-2.4 30.05,-2.26 30.05,-0.8 v1(29.65,-0.4)
  L5 w0.4: v1(9.118,-10.41) v1(9.118,-9.903) 8.275,-9.06 5.45,-9.06 4.75,-8.36 4.75,-5.235 4.4,-4.885 4.4,-1.635 8.25,2.215 8.25,7.947 9.3,8.997 9.3,9.646 11.769,12.115 14.143,12.115 15.675,10.583 15.675,8.665 v1(16.125,8.215)
  L6 w0.4: v1@29.645,-0.395 29.65,-0.39 v1(29.65,1.2)
  L6 w0.5: v1@9.1,-10.335 9.1,-9.921 v1(9.118,-9.903) 9.511,-9.51 11.614,-9.51 12.214,-10.11 19.1,-10.11 20.875,-8.335 23.35,-8.335 25.875,-5.81 25.875,-5.485 26.35,-5.01 26.725,-5.01 27.225,-4.51 27.225,-3.31 27.725,-2.81 v1@28.85,-2.81
  Bottom w0.2: C92.1@27.53,-4.135 27.53,-4 28.216,-4 28.45,-3.766 ; v1(28.85,-2.8) 28.45,-3.2 28.45,-3.766 ; v1(29.65,-0.4) 30.05,0 31.485,0 C91.1@31.77,-0.285 ; v1(29.65,0.4) 30.05,0.8 31.53,0.8 ; v1(29.65,1.2) 30.05,1.6 31.77,1.6 C94.1@31.77,1.665 ; C88.2@30.25,-5.26 29.65,-5.26 29.25,-4.86 29.25,-4.234 29.016,-4 28.684,-4 28.45,-3.766 ; C90.1@31.77,0.365 31.77,0.56 31.53,0.8 ; C89.1@31.77,1.04 31.53,0.8
  Bottom w0.3: C93.1@27.53,-3.435 28.05,-2.915 v1(28.05,-2.8)
  Bottom w0.4: 15.595,9.365 15.595,8.745 v1(16.125,8.215)
VDIO_LMS_LMK: C164.2 C165.2 C166.2 C167.2 FR18.2 IC7.14 IC7.18 | length 6
  Top w0.4: v1(16.7,8.375) 17.04,8.375 ; v1(16.8,10.25) 16.815,10.25 C166.2@17.175,9.89 ; C164.2@17.125,7.19 17.175,7.24 17.175,8.24 17.04,8.375 ; C167.2@17.175,8.89 17.175,8.51 17.04,8.375
  Bottom w0.3: v1(16.7,8.375) 16.155,8.92 16.155,9.365 16.155,10.07 16.335,10.25 v1(16.8,10.25) IC7.18@17.475,10.25
pads on no net: C1.0 C2.0 C3.0 C4.0 C5.0 C6.0 C7.0 C8.0 C9.0 C10.0 C11.0 C12.0 C13.0 C14.0 C15.0 C16.0 C17.0 C18.0 C19.0 C20.0 C21.0 C22.0 C23.0 C24.0 C25.0 C26.0 C27.0 C28.0 C29.0 C87.0 C88.0 C95.0 C102.0 C108.0 C112.0 C123.0 C124.0 C125.0 C126.0 C127.0 C128.0 C137.0 C140.0 C142.0 C144.0 C145.0 C147.0 C148.0 C149.0 C150.0 C151.0 C152.0 C153.0 C154.0 C155.0 C156.0 C157.0 C158.0 C159.0 C160.0 C161.0 C162.0 C163.0 C164.0 C165.0 C166.0 C167.0 C168.0 C169.0 C170.0 C171.0 C172.0 C173.0 C174.0 C175.0 C176.0 C177.0 C178.0 C179.0 C180.0 C181.0 C182.0 C183.0 C184.0 ESD3.9 ESD3.10 FL1.1 FR11.0 FR12.0 FR13.0 FR14.0 FR20.0 FR21.0 FR22.0 IC1.A5 IC1.A13 IC1.A21 IC1.AA1 IC1.AA3 IC1.AA5 IC1.AB2 IC1.AB4 IC1.AB6 IC1.AC3 IC1.AC5 IC1.AD2 IC1.AE1 IC1.AE5 IC1.AG3 IC1.AG33 IC1.AH2 IC1.AH4 IC1.AH32 IC1.AJ1 IC1.AJ3 IC1.AJ5 IC1.AJ11 IC1.AJ13 IC1.AJ21 IC1.AJ27 IC1.AJ29 IC1.AJ31 IC1.AJ33 IC1.AK2 IC1.AK4 IC1.AK6 IC1.AK8 IC1.AK10 IC1.AK26 IC1.AK28 IC1.AK30 IC1.AK32 IC1.AK34 IC1.AL3 IC1.AL5 IC1.AL7 IC1.AL9 IC1.AL11 IC1.AL27 IC1.AL29 IC1.AL31 IC1.AL33 IC1.AM4 IC1.AM6 IC1.AM8 IC1.AM10 IC1.AM12 IC1.AM28 IC1.AM30 IC1.AM34 IC1.AN3 IC1.AN5 IC1.AN7 IC1.AN11 IC1.AN27 IC1.AN29 IC1.AN31 IC1.AP6 IC1.AP30 IC1.AP32 IC1.B2 IC1.B4 IC1.B12 IC1.B14 IC1.B22 IC1.C1 IC1.C3 IC1.C5 IC1.C9 IC1.C11 IC1.C13 IC1.C15 IC1.C17 IC1.C19 IC1.C31 IC1.D2 IC1.D4 IC1.D8 IC1.D10 IC1.D12 IC1.D14 IC1.D18 IC1.D22 IC1.D30 IC1.D32 IC1.E3 IC1.E9 IC1.E11 IC1.E13 IC1.E15 IC1.E23 IC1.E29 IC1.E31 IC1.F2 IC1.F4 IC1.F10 IC1.F12 IC1.F14 IC1.F16 IC1.F22 IC1.F26 IC1.F32 IC1.G1 IC1.G29 IC1.J1 IC1.M2 IC1.M6 IC1.P2 IC1.R3 IC1.R5 IC1.T4 IC1.T6 IC1.U1 IC1.U3 IC1.U5 IC1.V2 IC1.V4 IC1.V6 IC1.W3 IC1.Y2 IC1.Y4 IC1.Y6 IC6.17 IC6.18 IC6.19 IC7.4 IC7.9 IC7.10 IC7.15 IC8.9 IC12.2 IC12.3 IC12.9 IC12.13 IC12.14 IC13.2 IC13.3 IC13.9 IC13.13 IC13.14 J4.6 J4.7 J4.8 J7.11 LED1.0 LED2.0 MN1.0 MN2.0 MN3.0 MN4.0 MN5.0 MN6.0 MN7.0 MN8.0 MN9.0 MN10.0 MN11.0 MN12.0 MN13.0 MN14.0 MN15.0 MN16.0 MN17.0 MN18.0 MN19.0 MN20.0 MN21.0 MN22.0 MN23.0 MN24.0 R1.0 R2.0 R3.0 R4.0 R5.0 R6.0 R7.0 R8.0 R9.0 R10.0 R11.0 R12.0 R13.0 R14.0 R15.0 R16.0 R17.0 R18.0 R19.0 R20.0 R21.0 R22.0 R23.0 R24.0 R25.0 R27.0 R28.0 R29.0 R30.0 R31.0 R34.0 R35.0 R36.0 R37.0 R38.0 R39.0 R40.0 R41.0 R42.0 R43.0 R44.0 R45.0 R46.0 R47.0 R48.0 R49.0 R50.0 R51.0 R52.0 R53.0 R54.0 R55.0 R56.0 R57.0 R58.0 R59.0 R60.0 R61.0 R62.0 R63.0 R64.0 R65.0 R66.0 R67.0 R68.0 R69.0 R70.0 R71.0 R72.0 R73.0 R74.0 R75.0 R76.0 R77.0 R78.0 R79.0 R80.0 R81.0 R82.0 R83.0 R84.0 R85.0 T1.NC T2.NC T3.NC T4.NC VT4.0 XO1.2 XO1.3 XO1.5 XO1.8 XO1.10 XT1.0
copper on no net: | length 238.6
  Top w0.2: 180,50 ccw(c182,50) 182,48 247,48 ccw(c247,50) 249,50 249,98 ccw(c247,98) 247,100 182,100 ccw(c182,98) 180,98 180,50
